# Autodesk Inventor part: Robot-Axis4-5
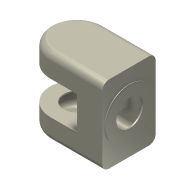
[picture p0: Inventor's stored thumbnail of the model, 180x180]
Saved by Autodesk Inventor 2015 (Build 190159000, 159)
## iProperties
Shininess: 21.0
Length Units: 11269
Angle Units: 11279
Time Units: 11290
Mass Units: 11283
Length Display Precision: 3
Angle Display Precision: 2
Created: 2001-08
Part Number: Robot-Axis4-5
Document SubType Name: ﾓﾃﾞﾘﾝｸﾞ
Designer: Administrator
Density: 1 g/cm^3
Material: Generic
Appearance: Smooth - Ivory
Density: 0.0
Volumn: 0.0
Area: 0.0
PropertySet Name: Model Information
Control State: 0
Master: False
Checked Out: False
Author: Administrator
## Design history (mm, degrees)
sketch "ｽｹｯﾁ1"
  geometry: L1 (0, -40)-(-118, -40); L2 (-118, -40)-(-118, 40); L3 (-118, 40)-(0, 40); L4 (0, 40)-(0, -40); L5 (-118, 0)-(0, 0); L6 (-78, 40)-(-78, -40); 2 further points
  constraints: 12 end point, 4 point on line, 3 midpoint, 2 horizontal, 2 parallel, 1 perpendicular, 1 vertical, 1 vertical alignment, 3 other
  dimensions: "d0" = 80 distance of L1.end L2.end; "d1" = 118 distance of L2.end L3.end
extrude "押し出し1" new body sketch "ｽｹｯﾁ1" stored distance "d2" = 116; taper "d3" = 0 deg
node "作業平面1"
sketch "ｽｹｯﾁ2"
  geometry: L1 (0, 40)-(-78, 40) reference; L2 (-78, -40)-(0, -40) reference; L3 (-38, 40)-(-38, -40); C1 r 40 at (-78, 0); A1 r 40 centre (-78, 0) between (-78, 40) and (-78, -40) reference
  constraints: 2 end point, 2 point on line, 1 centre point, 1 coincident, 1 concentric, 1 perpendicular, 1 tangent
extrude "押し出し2" cut sketch "ｽｹｯﾁ2" stored distance "d4" = 50; taper "d5" = 0 deg
sketch "ｽｹｯﾁ3"
  geometry: L1 (0, 0)-(0, 60) reference; L2 (-116, 60)-(-116, 0) reference; L3 (-116, 30)-(0, 30); L4 (-33, 70)-(-83, 70) reference; L5 (-58, 70)-(-58, -10); L6 (-83, -10)-(-33, -10) reference; C1 r 37 at (-58, 30)
  constraints: 5 midpoint, 4 end point, 1 centre point
  dimensions: "d7" = 74 diameter of C1
extrude "押し出し3" join sketch "ｽｹｯﾁ3" distance "d8" = 1; taper "d9" = 0 deg
node "作業軸1"
shell "Shell1" dims "d10" = 2
sketch "Sketch4"
  geometry: C1 r 37 at (0, 0) reference
hole "Hole1" sketch "Sketch4" at (0, 0) diameter "d11" = 40; stored, may be unused: countersink angle "d15" = 82 deg, drill point angle "d17" = 118 deg; dims "d12" = 6, "d13" = 4, "d14" = 2, "d16" = 2
sketch "Sketch5"
  geometry: A1 r 40 centre (-78, 0) between (-78, 40) and (-78, -40) reference
hole "Hole2" sketch "Sketch5" at (-78, 0) diameter "d18" = 40; stored, may be unused: countersink angle "d22" = 82 deg, drill point angle "d24" = 118 deg; dims "d19" = 6, "d20" = 4, "d21" = 2, "d23" = 2
sketch "Sketch6"
  geometry: A1 r 40 centre (78, 0) between (78, -40) and (78, 40) reference
hole "Hole3" sketch "Sketch6" at (78, 0) diameter "d25" = 40; stored, may be unused: countersink angle "d29" = 82 deg, drill point angle "d31" = 118 deg; dims "d26" = 6, "d27" = 4, "d28" = 2, "d30" = 2
body "Solid1"
fillet "Fillet1" dims "d6" = 10
